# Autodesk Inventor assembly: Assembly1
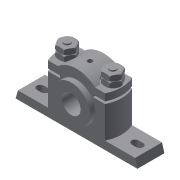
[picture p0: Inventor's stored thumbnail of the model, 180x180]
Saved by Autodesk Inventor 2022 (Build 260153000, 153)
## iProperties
Created: 2016-03
Part Number: Assembly1
Document SubType Name: Assembly
Designer: Sandeep
Author: Sandeep
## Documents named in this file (7)
- D:\PROJECTS_2021\Resources\Part Files\c13_Inv_2022_prt\fig-13-7\Plummer block assy\Assembly1.iam
- D:\PROJECTS_2021\Resources\Part Files\c13_Inv_2022_prt\fig-13-7\Plummer block assy\Casting.ipt
- D:\PROJECTS_2021\Resources\Part Files\c13_Inv_2022_prt\fig-13-7\Plummer block assy\Brasses.ipt
- D:\PROJECTS_2021\Resources\Part Files\c13_Inv_2022_prt\fig-13-7\Plummer block assy\Cap.ipt
- D:\PROJECTS_2021\Resources\Part Files\c13_Inv_2022_prt\fig-13-7\Plummer block assy\Bolt.ipt
- D:\PROJECTS_2021\Resources\Part Files\c13_Inv_2022_prt\fig-13-7\Plummer block assy\Nut.ipt
- D:\PROJECTS_2021\Resources\Part Files\c13_Inv_2022_prt\fig-13-7\Plummer block assy\Lock Nut.ipt
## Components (9 placed, 6 different names)
1. Casting:1 — Mate:1, Mate:2, Insert:1, Insert:2, Angle:1, Angle:2
2. Brasses:1 — Mate:1, Mate:2, Mate:3, Mate:4
3. Cap:1 — Mate:3, Mate:4, Insert:3, Insert:5
4. Bolt:1 — Insert:1, Angle:1
5. Bolt:2 — Insert:2, Angle:2
6. Nut:1 — Insert:3, Insert:4
7. Nut:2 — Insert:5, Insert:6
8. Lock Nut:1 — Insert:4
9. Lock Nut:2 — Insert:6
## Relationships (12: Insert 6, Mate 4, Angle 2)
- Mate:1: Casting:1 ↔ Brasses:1
- Mate:2: Casting:1 ↔ Brasses:1
- Mate:3: Brasses:1 ↔ Cap:1
- Mate:4: Brasses:1 ↔ Cap:1
- Insert:1: Casting:1 ↔ Bolt:1
- Insert:2: Casting:1 ↔ Bolt:2
- Angle:1: Casting:1 ↔ Bolt:1
- Angle:2: Casting:1 ↔ Bolt:2
- Insert:3: Cap:1 ↔ Nut:1
- Insert:4: Nut:1 ↔ Lock Nut:1
- Insert:5: Cap:1 ↔ Nut:2
- Insert:6: Nut:2 ↔ Lock Nut:2
